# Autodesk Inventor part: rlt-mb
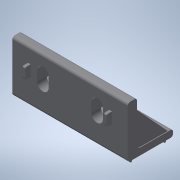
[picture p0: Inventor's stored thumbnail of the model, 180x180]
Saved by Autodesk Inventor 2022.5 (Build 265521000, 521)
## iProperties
Created: 2016-12
Part Number: rlt-mb
Material: 一般
Document SubType Name: Modeling
Designer: imaocorp
Density: 1 g/cm^3
Appearance: 既定
Author: imaocorp
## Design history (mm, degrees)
node "rlt-mb.x_t1"
node "rlt-mb"
node "Base1"
